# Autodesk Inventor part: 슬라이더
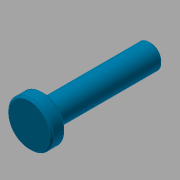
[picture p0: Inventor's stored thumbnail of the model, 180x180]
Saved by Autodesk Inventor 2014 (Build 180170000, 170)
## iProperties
Created: 2019-01
Part Number: 슬라이더
Material: 강철, 연강
Document SubType Name: Modeling
Designer: mduedu
Density: 7.86 g/cm^3
Appearance: 하늘색 중간
Mass: 105.846 g
Surface Area: 45.0711 cm^2
Volume: 13.4664 cm^3
Author: mduedu
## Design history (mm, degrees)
sketch "스케치1"
  geometry: L1 (0, 0)-(8, 0); L2 (8, 0)-(8, 13); L3 (8, 13)-(0, 13); L4 (0, 13)-(0, 0); L5 (8, 0)-(70, 0); L6 (70, 0)-(70, 7); L7 (70, 7)-(8, 7); L8 (8, 7)-(8, 0)
  constraints: 16 end point, 4 parallel, 2 horizontal, 2 perpendicular
  dimensions: "d0" = 70 distance between parallel lines of L6 L4; "d2" = 8 distance of L2.end L3.end; "d3" = 26 diameter of L3 L1; "d4" = 14 diameter of L7 L5
revolve "회전1" sketch "스케치1" stored, may be unused: angle "d5" = 90 deg
chamfer "모따기1" distance "d6" = 1; stored, may be unused: second distance "d7" = 2, angle "d8" = 45 deg
hole "구멍1" diameter "d14" = 4.134; stored, may be unused: countersink angle "d18" = 60 deg, drill point angle "d20" = 118 deg; dims "d15" = 12, "d16" = 6.3, "d17" = 2, "d19" = 15, "d26" = 10, "d27" = 10
chamfer "모따기4" distance "d24" = 1; stored, may be unused: second distance "d25" = 2, angle "d28" = 30 deg
sketch "스케치2"
  geometry: L1 (70, 2.067)-(70, -2.067) reference; L2 (70, 0)-(68, 0); L3 (68, 0)-(68, 2.067); L4 (70, 3.222)-(70, 0); L5 (70, 3.222)-(68, 2.067); L6 (55, 2.067)-(70, 2.067) reference; 1 further point
  constraints: 8 end point, 1 horizontal, 1 midpoint, 1 parallel, 1 perpendicular, 1 point on line
  dimensions: "d29" = 2 horizontal distance of L4.start L3.end; "d31" = 30 deg angle of L2 L5
revolve "회전2" sketch "스케치2" stored, may be unused: angle "d33" = 90 deg
node "솔리드1"
